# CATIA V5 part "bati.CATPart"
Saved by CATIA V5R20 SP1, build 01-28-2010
Part number: bati
Bounding box of the stored display mesh (mm): x -40 to 300.258, y -170 to 7.312, z -20 to 45
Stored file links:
  E:\EDELI\wjacquemont\Edeli_2012_122_wjacquemont\bati.CATPart
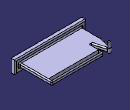
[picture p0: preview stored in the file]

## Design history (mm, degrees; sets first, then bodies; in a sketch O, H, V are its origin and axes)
Body1 (main body)
  Sketch1 on xy-plane, origin (0, 0, 0), H (1, 0, 0), V (0, 1, 0)
    arc A1 centre (0, 0) radius 7.5 from (7.5, 0) to (-7.5, 0) ccw
    line L1 (-7.5, 0) -> (-20, -60)
    point P1 (-7.5, 0)
    line L2 (7.5, 0) -> (25.258, -60)
    point P3 (7.5, 0)
    line L3 (25.258, -60) -> (193.393, -60)
    line L4 (193.393, -60) -> (193.393, -70)
    line L5 (193.393, -70) -> (-20, -70)
    line L6 (-20, -70) -> (-20, -60)
    radius A1 = 7.5
    coincidence: P1 H, P3 H
    horizontal: L3 H, L5 H
    vertical: L4 V, L6 V
  Pad1: profile Sketch1, direction (0, 0, 1), length 20
  Sketch2 on end face of Pad1, origin (0, 0, 20), H (1, 0, 0), V (0, 1, 0)
    circle A1 centre (0, 0) radius 5
    reference projected arc E1 centre (0, 0) radius 7.5 from (7.5, 0) to (-7.5, 0) ccw from edge [face of Pad1 from Sketch1.A1 | end face of Pad1]
    radius A1 = 5
    concentricity: A1 E1
  Pad2: profile Sketch2, direction (0, 0, 1), length 25
  Sketch3 on face of Pad1 from Sketch1.L3, origin (0, -60, 0), H (-1, 0, 0), V (0, 0, 1)
    line L1 (-30.258, 20) -> (-280.258, 20)
    line L2 (-280.258, 20) -> (-280.258, 0)
    line L3 (-280.258, 0) -> (-30.258, 0)
    line L4 (-30.258, 0) -> (-30.258, 20)
    reference projected line E1 (-193.393, 0) -> (-25.258, 0) from edge [start face of Pad1 | face of Pad1 from Sketch1.L3]
    reference projected line E2 (-193.393, 20) -> (-25.258, 20) from edge [face of Pad1 from Sketch1.L3 | end face of Pad1]
    reference projected line E3 (-25.258, 0) -> (-25.258, 20) from edge [face of Pad1 from Sketch1.L2 | face of Pad1 from Sketch1.L3]
    distance L4 E3 = 5
    length L3 = 250
    horizontal: L1 H, L3 H
    vertical: L2 V, L4 V
    coincidence: L3 E1, E2 L1
  Pad3: profile Sketch3, direction (0, 1, 0), length 65
  Sketch4 on face of Pad3, origin (0, 0, 20), H (1, 0, 0), V (0, 1, 0)
    line L1 (35.258, 0) -> (275.258, 0)
    line L2 (275.258, 0) -> (275.258, -15)
    line L3 (275.258, -15) -> (35.258, -15)
    line L4 (35.258, -15) -> (35.258, 0)
    reference projected line E1 (280.258, -60) -> (280.258, -10) from edge [face of Pad3 from Sketch3.L2 | face of Pad3 from Sketch3.L1]
    reference projected line E2 (30.258, -60) -> (30.258, -10) from edge [face of Pad3 | face of Pad3 from Sketch3.L4]
    reference projected line E3 (40.258, 5) -> (290.258, 5) from edge [face of Pad3 from Sketch3.L1 | end face of Pad3]
    distance L2 E1 = 5
    distance L4 E2 = 5
    distance L1 E3 = 5
    distance L3 L1 = 15
    horizontal: L1 H, L3 H
    vertical: L2 V, L4 V
  Pocket1: profile Sketch4, direction (0, 0, -1), length 15
  Sketch5 on face of Pad1 from Sketch1.L5, origin (0, -70, 0), H (1, 0, 0), V (0, 0, 1)
    point P1 (193.393, 20)
    line L1 (193.393, 20) -> (280.258, 20)
    line L2 (280.258, 20) -> (280.258, 0)
    line L3 (280.258, 0) -> (193.393, 0)
    line L4 (193.393, 0) -> (193.393, 20)
    point P3 (280.258, 0)
    reference projected point E1 (280.258, 0) from vertex [start face of Pad3 | face of Pad3 from Sketch3.L3 | face of Pad3 from Sketch3.L2]
    reference projected point E2 (193.393, 20) from vertex [face of Pad1 from Sketch1.L4 | end face of Pad1 | face of Pad1 from Sketch1.L5]
    horizontal: L1 H, L3 H
    vertical: L2 V, L4 V
    coincidence: E1 P3, P1 E2
  Pad4: profile Sketch5, direction (0, 1, 0), length 10
  Sketch6 on face of Pad4, origin (0, -70, 0), H (1, 0, 0), V (0, 0, 1)
    point P1 (-20, 20)
    line L1 (-20, 20) -> (280.258, 20)
    line L2 (280.258, 20) -> (280.258, 0)
    line L3 (280.258, 0) -> (-20, 0)
    line L4 (-20, 0) -> (-20, 20)
    point P3 (280.258, 0)
    reference projected point E1 (280.258, 0) from vertex [face of Pad4 | face of Pad4 | face of Pad4]
    reference projected point E2 (-20, 20) from vertex [face of Pad4 | face of Pad1 from Sketch1.L6 | face of Pad4]
    horizontal: L1 H, L3 H
    vertical: L2 V, L4 V
    coincidence: P3 E1, P1 E2
  Pad5: profile Sketch6, direction (0, -1, 0), length 80
  Sketch7 on end face of Pad5, origin (0, -150, 0), H (1, 0, 0), V (0, 0, 1)
    line L1 (300.258, 40) -> (-40, 40)
    line L2 (-40, 40) -> (-40, -20)
    line L3 (-40, -20) -> (300.258, -20)
    line L4 (300.258, -20) -> (300.258, 40)
    reference projected line E1 (-20, 0) -> (280.258, 0) from edge [face of Pad5 | end face of Pad5]
    reference projected line E2 (280.258, 20) -> (-20, 20) from edge [face of Pad5 | end face of Pad5]
    reference projected line E3 (280.258, 0) -> (280.258, 20) from edge [face of Pad5 | end face of Pad5]
    reference projected line E4 (-20, 20) -> (-20, 0) from edge [face of Pad5 | end face of Pad5]
    distance L3 E1 = 20
    distance E2 L1 = 20
    distance E3 L4 = 20
    distance E4 L2 = 20
    horizontal: L1 H, L3 H
    vertical: L2 V, L4 V
  Pad6: profile Sketch7, direction (0, -1, 0), length 20
  Fillet1: radius 5, on edge [start face of Pad6 | face of Pad6 from Sketch7.L1]; edge [face of Pad5 | start face of Pad6] (x4); edge [start face of Pad6 | face of Pad6 from Sketch7.L4]; edge [start face of Pad6 | face of Pad6 from Sketch7.L2]; edge [start face of Pad6 | face of Pad6 from Sketch7.L3]; edge [face of Pad5 | face of Pad5] (x2); edge [face of Pad5 | end face of Pad3] (x2); face of Pad5; edge [face of Pad3 from Sketch3.L4 | end face of Pad3]; edge [face of Pad3 from Sketch3.L4 | face of Pad5]; edge [face of Pad5 | face of Pad3 from Sketch3.L4]
  Fillet2: radius 5, on edge [face of Pad5 | face of Pad5] (x2); edge [face of Pad5 | face of Pad1 from Sketch1.L1]; edge [face of Pad1 from Sketch1.L1 | face of Pad5]; edge [face of Pad5 | face of Pad1 from Sketch1.L2]; edge [face of Pad1 from Sketch1.L2 | face of Pad5]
